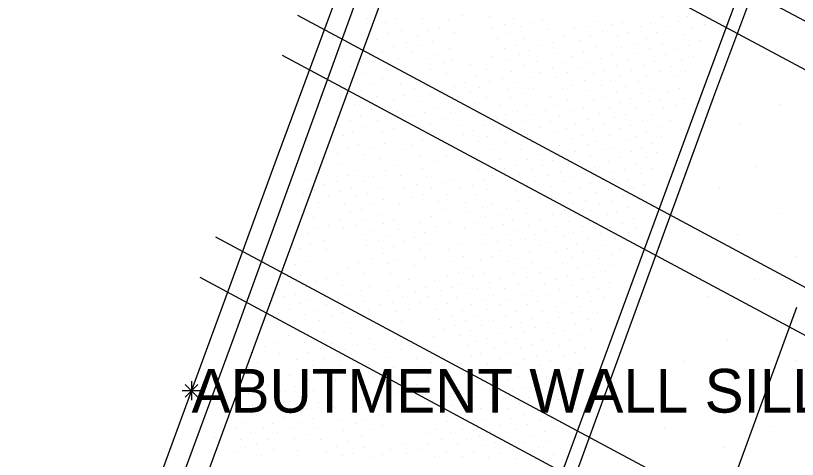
# Model space of a CAD drawing. Extents: x 1729983 to 1730242, y 468641 to 469019.
# Drawn here: x 1730044.55 to 1730076.74, y 468830.28 to 468848.55 of the extents above; entities that cross this region are included whole.
import ezdxf

# ---------------------------------------------------------------- set-up
doc = ezdxf.new("R2010")
doc.units = 0
for name, color, linetype in [('Default', 7, 'Continuous'), ('S_Bridge_Abutment_Bottom', 7, 'Continuous'), ('S_Curb_Type_1', 7, 'Continuous'), ('S_Ground_SpotElevation', 7, 'Continuous'), ('S_Misc_MiscFeature', 7, 'Continuous'), ('S_Misc_MiscItems', 7, 'Continuous'), ('S_Roadway_Edge_Pavement', 7, 'Continuous'), ('S_Text', 7, 'Continuous'), ('S_Utilities_AG_Communications', 7, 'Continuous')]:
    doc.layers.add(name, color=color, linetype=linetype)

# ---------------------------------------------------------------- blocks, each defined once
blk = doc.blocks.new('POINT_DISPLAY')
at = {"layer": 'Default'}
blk.add_line((0, 0), (0, 0), dxfattribs=at)

msp = doc.modelspace()

# ---------------------------------------------------------------- linework, layer by layer
at = {"layer": 'S_Bridge_Abutment_Bottom'}
msp.add_lwpolyline([(1730028.397, 468777.334), (1730030.386, 468778.233), (1730033.055, 468779.454), (1730033.218, 468779.896), (1730038.37, 468793.886), (1730045.609, 468813.805), (1730053.552, 468835.326), (1730061.264, 468856.585), (1730068.104, 468874.933), (1730077.288, 468899.639), (1730081.24, 468910.357), (1730081.674, 468911.604), (1730082.174, 468913.008), (1730079.112, 468916.385)], dxfattribs=at)
at = {"layer": 'S_Curb_Type_1'}
msp.add_lwpolyline([(1730127.344, 469003.745), (1730128.313, 469003.209), (1730129.005, 469001.957), (1730128.001, 468995.343), (1730121.966, 468978.7), (1730114.875, 468959.641), (1730107.952, 468940.794), (1730100.667, 468921.305), (1730089.464, 468890.124), (1730080.18, 468865.229), (1730072.814, 468845.368), (1730066.167, 468827.336), (1730059.271, 468808.011), (1730050.413, 468784.194), (1730032.961, 468736.85), (1730026.597, 468719.521), (1730017.926, 468696.116)], dxfattribs=at)
at = {"layer": 'S_Misc_MiscFeature'}
for p, q in [((1730084.047, 468844.582), (1730059.664, 468857.636)), ((1730083.323, 468842.964), (1730058.908, 468856.045)), ((1730081.008, 468835.237), (1730056.175, 468848.547)), ((1730080.253, 468833.664), (1730055.544, 468846.9)), ((1730077.695, 468826.086), (1730052.791, 468839.429)), ((1730076.906, 468824.473), (1730052.142, 468837.765)), ((1730073.388, 468827.447), (1730076.726, 468836.539))]:
    msp.add_line(p, q, dxfattribs=at)
msp.add_lwpolyline([(1730028.819, 468777.529), (1730031.975, 468779.199), (1730034.887, 468787.021), (1730045.144, 468814.963), (1730055.236, 468842.487), (1730058.712, 468851.879), (1730068.635, 468878.922), (1730072.147, 468888.181), (1730075.727, 468897.903), (1730078.619, 468905.503), (1730081.717, 468913.484), (1730079.668, 468915.827)], dxfattribs=at)
at = {"layer": 'S_Misc_MiscItems'}
for p, q in [((1730052.056, 468832.839), (1730051.532, 468833.363)), ((1730052.056, 468833.363), (1730051.532, 468832.839)), ((1730051.794, 468833.494), (1730051.794, 468832.708)), ((1730052.187, 468833.101), (1730051.401, 468833.101))]:
    msp.add_line(p, q, dxfattribs=at)
at = {"layer": 'S_Roadway_Edge_Pavement'}
msp.add_lwpolyline([(1730128.624, 468995.344), (1730122.317, 468978.183), (1730114.717, 468957.613), (1730108.465, 468940.563), (1730101.987, 468923.258), (1730100.18, 468918.245), (1730089.85, 468889.621), (1730080.624, 468864.761), (1730073.33, 468845.31), (1730066.507, 468826.616), (1730059.612, 468807.458), (1730050.88, 468783.514), (1730042.113, 468759.912), (1730034.557, 468739.828), (1730031.891, 468732.687), (1730026.743, 468718.512), (1730018.434, 468695.905)], dxfattribs=at)
at = {"layer": 'S_Utilities_AG_Communications'}
msp.add_lwpolyline([(1730120.945, 469004.632), (1730097.184, 468954.408), (1730085.556, 468926.546), (1730082.304, 468910.964), (1730034.658, 468781.323), (1729998.254, 468703.261)], dxfattribs=at)

# ---------------------------------------------------------------- block references
at = {"layer": 'S_Ground_SpotElevation'}
for p in [(1730062.952, 468848.542), (1730064.062, 468848.518), (1730071.178, 468848.493), (1730072.214, 468848.507), (1730059.055, 468848.442), (1730059.76, 468848.264), (1730060.209, 468848.413), (1730061.314, 468848.415), (1730062.367, 468848.381), (1730064.686, 468848.19), (1730065.048, 468848.443), (1730065.736, 468848.278), (1730066.234, 468848.397), (1730068.526, 468848.326), (1730069.149, 468848.179), (1730069.543, 468848.255), (1730070.689, 468848.204), (1730071.84, 468848.291), (1730072.92, 468848.169), (1730059.237, 468848.015), (1730060.426, 468847.932), (1730061.519, 468847.952), (1730061.988, 468848.067), (1730062.628, 468847.846), (1730064.139, 468848.033), (1730065.334, 468848.088), (1730066.45, 468847.984), (1730067.572, 468848.015), (1730068.055, 468848.1), (1730068.714, 468847.91), (1730069.776, 468847.862), (1730070.296, 468848.094), (1730070.936, 468847.869), (1730071.353, 468848.11), (1730072.432, 468848.046), (1730058.797, 468847.751), (1730059.427, 468847.553), (1730059.901, 468847.801), (1730061.081, 468847.675), (1730064.386, 468847.615), (1730064.887, 468847.821), (1730065.456, 468847.591), (1730067.119, 468847.677), (1730067.809, 468847.523), (1730068.228, 468847.732), (1730069.331, 468847.705), (1730070.52, 468847.612), (1730072.052, 468847.773), (1730072.756, 468847.537), (1730060.119, 468847.257), (1730060.629, 468847.453), (1730061.276, 468847.319), (1730061.714, 468847.483), (1730062.401, 468847.214), (1730065.128, 468847.312), (1730066.215, 468847.336), (1730066.67, 468847.451), (1730068.419, 468847.272), (1730069.499, 468847.254), (1730070.03, 468847.407), (1730070.658, 468847.204), (1730071.174, 468847.358), (1730072.258, 468847.31), (1730058.601, 468847.181), (1730059.67, 468847.025), (1730060.862, 468847.027), (1730061.913, 468846.966), (1730064.667, 468847.179), (1730065.304, 468846.929), (1730065.686, 468847.11), (1730066.878, 468847), (1730067.474, 468846.882), (1730067.953, 468847.065), (1730069.122, 468846.943), (1730070.172, 468847.001), (1730071.316, 468846.946), (1730071.819, 468847.169), (1730075.469, 468846.915), (1730058.749, 468846.658), (1730059.236, 468846.809), (1730059.976, 468846.61), (1730060.325, 468846.788), (1730061.45, 468846.781), (1730062.165, 468846.617), (1730062.556, 468846.756), (1730064.187, 468846.866), (1730064.778, 468846.683), (1730065.984, 468846.671), (1730067.09, 468846.634), (1730068.196, 468846.607), (1730068.624, 468846.787), (1730069.783, 468846.692), (1730070.856, 468846.647), (1730071.96, 468846.693), (1730072.45, 468846.874), (1730058.36, 468846.456), (1730061.638, 468846.317), (1730063.274, 468846.516), (1730063.957, 468846.335), (1730064.965, 468846.264), (1730065.502, 468846.502), (1730066.671, 468846.375), (1730067.748, 468846.421), (1730068.819, 468846.306), (1730069.287, 468846.509), (1730069.915, 468846.297), (1730070.411, 468846.488), (1730071.059, 468846.241), (1730071.547, 468846.438), (1730072.151, 468846.252), (1730058.516, 468846.018), (1730058.97, 468846.153), (1730059.641, 468845.96), (1730060.766, 468845.939), (1730062.305, 468846.154), (1730063.477, 468846.098), (1730064.602, 468845.973), (1730065.745, 468846.008), (1730066.128, 468846.186), (1730066.823, 468846.016), (1730067.267, 468846.219), (1730068.342, 468846.164), (1730069.464, 468846.057), (1730070.55, 468846.081), (1730071.673, 468846.044), (1730058.065, 468845.752), (1730059.179, 468845.753), (1730060.392, 468845.697), (1730061.462, 468845.674), (1730062.606, 468845.623), (1730063.04, 468845.799), (1730064.061, 468845.818), (1730065.23, 468845.787), (1730067.468, 468845.653), (1730067.969, 468845.87), (1730068.665, 468845.675), (1730069.049, 468845.858), (1730069.681, 468845.638), (1730070.207, 468845.833), (1730058.261, 468845.332), (1730058.765, 468845.483), (1730060.958, 468845.543), (1730061.626, 468845.285), (1730062.08, 468845.475), (1730063.269, 468845.388), (1730063.659, 468845.58), (1730064.796, 468845.513), (1730065.402, 468845.358), (1730065.859, 468845.544), (1730067.055, 468845.532), (1730068.163, 468845.483), (1730069.292, 468845.393), (1730070.333, 468845.339), (1730070.823, 468845.523), (1730071.435, 468845.363), (1730071.89, 468845.567), (1730057.906, 468845.118), (1730059.026, 468845.096), (1730059.423, 468845.231), (1730060.105, 468845.101), (1730060.566, 468845.262), (1730061.158, 468845.003), (1730062.357, 468844.964), (1730062.769, 468845.221), (1730063.926, 468845.158), (1730064.944, 468845.158), (1730066.584, 468845.219), (1730067.256, 468845.086), (1730068.356, 468845.079), (1730068.832, 468845.164), (1730069.432, 468844.967), (1730069.874, 468845.135), (1730070.614, 468844.993), (1730071.071, 468845.104), (1730072.077, 468845.116), (1730058.505, 468844.875), (1730059.193, 468844.676), (1730061.916, 468844.723), (1730063.457, 468844.922), (1730064.489, 468844.863), (1730065.589, 468844.866), (1730066.356, 468844.641), (1730066.745, 468844.845), (1730067.401, 468844.655), (1730067.928, 468844.74), (1730069.012, 468844.743), (1730070.118, 468844.779), (1730071.248, 468844.727), (1730071.728, 468844.837), (1730076.053, 468844.901), (1730058.732, 468844.38), (1730060.257, 468844.588), (1730060.941, 468844.396), (1730061.388, 468844.551), (1730062.111, 468844.309), (1730062.457, 468844.545), (1730063.614, 468844.522), (1730064.713, 468844.477), (1730065.215, 468844.599), (1730065.856, 468844.464), (1730066.938, 468844.411), (1730068.614, 468844.501), (1730069.214, 468844.358), (1730069.675, 468844.474), (1730070.766, 468844.461), (1730057.866, 468844.037), (1730058.323, 468844.239), (1730058.961, 468843.999), (1730059.431, 468844.227), (1730060.532, 468844.204), (1730061.639, 468844.073), (1730062.788, 468844.035), (1730063.82, 468844.005), (1730064.346, 468844.294), (1730065.413, 468844.2), (1730066.587, 468844.17), (1730067.599, 468844.118), (1730068.137, 468844.281), (1730068.791, 468844.114), (1730069.875, 468844.035), (1730070.37, 468844.218), (1730071.03, 468844), (1730071.5, 468844.237), (1730074.404, 468844.097), (1730058.43, 468843.779), (1730059.642, 468843.753), (1730060.095, 468843.891), (1730061.132, 468843.935), (1730063.357, 468843.8), (1730064.475, 468843.842), (1730064.92, 468843.93), (1730065.609, 468843.674), (1730066.134, 468843.94), (1730066.72, 468843.78), (1730067.222, 468843.894), (1730068.311, 468843.87), (1730069.423, 468843.886), (1730070.543, 468843.786), (1730057.596, 468843.335), (1730058.066, 468843.61), (1730061.293, 468843.441), (1730061.796, 468843.654), (1730062.47, 468843.396), (1730062.979, 468843.642), (1730063.59, 468843.372), (1730063.996, 468843.568), (1730065.808, 468843.348), (1730067.443, 468843.504), (1730067.883, 468843.607), (1730068.49, 468843.385), (1730068.99, 468843.593), (1730069.687, 468843.397), (1730070.106, 468843.552), (1730071.13, 468843.557), (1730058.242, 468843.07), (1730058.647, 468843.248), (1730059.283, 468843.117), (1730059.734, 468843.271), (1730060.475, 468843.04), (1730060.858, 468843.208), (1730064.248, 468843.051), (1730064.728, 468843.324), (1730065.345, 468843.027), (1730066.481, 468843.126), (1730066.93, 468843.19), (1730068.139, 468843.224), (1730068.718, 468843.042), (1730069.181, 468843.119), (1730070.325, 468843.121), (1730070.742, 468843.295), (1730057.815, 468842.88), (1730058.899, 468842.84), (1730061.166, 468842.757), (1730062.277, 468842.793), (1730063.341, 468842.74), (1730066.093, 468842.826), (1730067.192, 468842.771), (1730067.623, 468842.95), (1730068.218, 468842.806), (1730069.913, 468842.953), (1730070.537, 468842.701), (1730070.926, 468842.909), (1730056.87, 468842.521), (1730057.356, 468842.664), (1730057.97, 468842.463), (1730059.53, 468842.658), (1730060.144, 468842.372), (1730061.793, 468842.546), (1730064.014, 468842.412), (1730064.486, 468842.64), (1730065.135, 468842.379), (1730065.628, 468842.637), (1730066.651, 468842.594), (1730067.363, 468842.416), (1730067.783, 468842.544), (1730068.973, 468842.528), (1730069.402, 468842.688), (1730070.121, 468842.467), (1730057.067, 468842.08), (1730058.646, 468842.159), (1730059.794, 468842.157), (1730061.296, 468842.264), (1730063.604, 468842.204), (1730064.693, 468842.266), (1730065.828, 468842.223), (1730066.227, 468842.364), (1730066.968, 468842.099), (1730068.031, 468842.053), (1730068.404, 468842.312), (1730069.19, 468842.108), (1730069.64, 468842.225), (1730070.274, 468842.063), (1730070.766, 468842.234), (1730075.039, 468842.352), (1730056.65, 468841.808), (1730058.214, 468841.975), (1730058.854, 468841.733), (1730059.274, 468841.91), (1730060.386, 468841.952), (1730061.484, 468841.904), (1730062.594, 468841.804), (1730063.838, 468841.818), (1730064.18, 468841.97), (1730064.855, 468841.782), (1730065.304, 468842.015), (1730066.469, 468841.969), (1730067.517, 468841.903), (1730068.703, 468841.8), (1730069.803, 468841.747), (1730057.236, 468841.601), (1730057.774, 468841.714), (1730058.378, 468841.477), (1730059.493, 468841.454), (1730060.571, 468841.46), (1730061.052, 468841.592), (1730061.69, 468841.434), (1730062.251, 468841.678), (1730062.814, 468841.446), (1730063.374, 468841.562), (1730065.598, 468841.455), (1730065.966, 468841.717), (1730066.63, 468841.526), (1730067.101, 468841.71), (1730067.769, 468841.442), (1730068.238, 468841.638), (1730069.355, 468841.635), (1730069.993, 468841.433), (1730070.407, 468841.608), (1730073.519, 468841.464), (1730056.413, 468841.207), (1730056.86, 468841.344), (1730057.42, 468841.102), (1730057.908, 468841.32), (1730058.533, 468841.091), (1730059.04, 468841.243), (1730061.333, 468841.194), (1730062.329, 468841.193), (1730063.501, 468841.187), (1730063.965, 468841.382), (1730065.158, 468841.343), (1730067.339, 468841.256), (1730068.482, 468841.258), (1730068.961, 468841.377), (1730069.594, 468841.091), (1730057.007, 468840.856), (1730058.096, 468840.831), (1730059.281, 468840.826), (1730059.678, 468840.987), (1730060.371, 468840.764), (1730060.84, 468841.061), (1730061.948, 468840.896), (1730063.07, 468840.856), (1730064.181, 468840.83), (1730065.267, 468840.922), (1730065.724, 468841.078), (1730066.794, 468841.027), (1730067.473, 468840.818), (1730068.017, 468840.942), (1730068.591, 468840.786), (1730069.096, 468840.907), (1730070.229, 468840.971), (1730056.163, 468840.506), (1730058.33, 468840.461), (1730058.808, 468840.551), (1730062.124, 468840.545), (1730063.227, 468840.477), (1730063.783, 468840.638), (1730064.78, 468840.626), (1730067.145, 468840.54), (1730068.278, 468840.522), (1730069.313, 468840.45), (1730069.782, 468840.651), (1730056.834, 468840.231), (1730057.873, 468840.133), (1730058.959, 468840.162), (1730059.473, 468840.349), (1730060.117, 468840.143), (1730061.69, 468840.29), (1730063.894, 468840.291), (1730064.418, 468840.366), (1730065.015, 468840.129), (1730065.581, 468840.411), (1730066.18, 468840.129), (1730066.666, 468840.345), (1730067.704, 468840.329), (1730068.906, 468840.342), (1730069.975, 468840.182), (1730075.956, 468840.383), (1730055.884, 468839.852), (1730056.965, 468839.806), (1730057.437, 468839.92), (1730058.551, 468839.886), (1730059.708, 468839.979), (1730061.237, 468840.029), (1730061.893, 468839.877), (1730062.423, 468840.038), (1730063.022, 468839.837), (1730063.448, 468840.022), (1730064.125, 468839.816), (1730064.638, 468839.961), (1730065.668, 468839.903), (1730066.783, 468839.857), (1730067.306, 468840.077), (1730067.911, 468839.881), (1730068.451, 468840.083), (1730069.061, 468839.814), (1730069.534, 468839.98), (1730070.117, 468839.792), (1730056.581, 468839.557), (1730058.056, 468839.767), (1730058.845, 468839.521), (1730059.169, 468839.712), (1730060.331, 468839.724), (1730061.4, 468839.619), (1730063.771, 468839.551), (1730064.887, 468839.522), (1730065.205, 468839.709), (1730065.974, 468839.549), (1730066.381, 468839.711), (1730067.542, 468839.627), (1730068.642, 468839.569), (1730069.779, 468839.624), (1730074.258, 468839.532), (1730056.703, 468839.164), (1730057.245, 468839.295), (1730059.48, 468839.281), (1730059.957, 468839.449), (1730060.527, 468839.262), (1730060.985, 468839.429), (1730061.599, 468839.179), (1730062.806, 468839.175), (1730064.404, 468839.267), (1730065.536, 468839.323), (1730066.552, 468839.22), (1730067.111, 468839.44), (1730067.657, 468839.157), (1730068.15, 468839.367), (1730069.251, 468839.382), (1730056.262, 468838.962), (1730057.352, 468838.927), (1730058.99, 468839.077), (1730060.097, 468839.039), (1730061.162, 468838.933), (1730062.365, 468838.908), (1730063.913, 468839.107), (1730064.526, 468838.887), (1730064.979, 468839.065), (1730066.147, 468839.069), (1730066.826, 468838.831), (1730067.26, 468838.943), (1730068.374, 468838.882), (1730068.852, 468839.1), (1730069.458, 468838.92), (1730059.187, 468838.554), (1730059.709, 468838.774), (1730060.265, 468838.524), (1730061.391, 468838.569), (1730062.995, 468838.634), (1730064.165, 468838.635), (1730065.231, 468838.543), (1730065.731, 468838.824), (1730067.487, 468838.607), (1730067.924, 468838.781), (1730068.602, 468838.532), (1730069.081, 468838.7), (1730076.684, 468838.626), (1730056.071, 468838.304), (1730056.543, 468838.42), (1730058.688, 468838.368), (1730059.853, 468838.36), (1730060.992, 468838.248), (1730062.584, 468838.444), (1730063.258, 468838.194), (1730063.678, 468838.449), (1730064.801, 468838.434), (1730065.842, 468838.397), (1730066.534, 468838.193), (1730067.06, 468838.331), (1730068.179, 468838.271), (1730069.167, 468838.27), (1730055.171, 468837.88), (1730055.575, 468838.049), (1730057.782, 468837.942), (1730058.274, 468838.131), (1730058.887, 468837.93), (1730059.993, 468837.921), (1730062.782, 468837.971), (1730063.877, 468837.931), (1730065.045, 468837.92), (1730065.441, 468838.171), (1730066.124, 468837.963), (1730067.687, 468838.15), (1730068.822, 468838.011), (1730055.813, 468837.586), (1730056.296, 468837.855), (1730056.88, 468837.593), (1730057.347, 468837.738), (1730060.735, 468837.663), (1730061.791, 468837.658), (1730062.331, 468837.851), (1730063.356, 468837.791), (1730064.075, 468837.55), (1730064.48, 468837.74), (1730065.631, 468837.756), (1730066.767, 468837.693), (1730067.271, 468837.852), (1730067.905, 468837.664), (1730068.355, 468837.77), (1730069.006, 468837.555), (1730074.983, 468837.697), (1730055.32, 468837.332), (1730056.483, 468837.374), (1730058.027, 468837.444), (1730058.761, 468837.23), (1730059.141, 468837.413), (1730059.874, 468837.23), (1730060.327, 468837.402), (1730061.422, 468837.364), (1730062.038, 468837.226), (1730062.547, 468837.369), (1730062.905, 468837.533), (1730063.586, 468837.296), (1730064.69, 468837.293), (1730065.258, 468837.459), (1730065.818, 468837.235), (1730066.346, 468837.49), (1730066.954, 468837.266), (1730067.45, 468837.425), (1730068.571, 468837.331), (1730054.896, 468837.12), (1730055.622, 468836.964), (1730056.059, 468837.081), (1730057.113, 468837.11), (1730058.167, 468837.067), (1730060.478, 468837.002), (1730061.004, 468837.189), (1730061.527, 468836.966), (1730062.704, 468836.949), (1730063.101, 468837.101), (1730064.247, 468837.018), (1730065.42, 468837.085), (1730066.531, 468837.064), (1730067.633, 468836.994), (1730068.115, 468837.188), (1730068.817, 468836.925), (1730073.097, 468837.002), (1730055.108, 468836.763), (1730056.24, 468836.689), (1730056.644, 468836.852), (1730057.369, 468836.641), (1730057.827, 468836.842), (1730058.891, 468836.793), (1730059.565, 468836.633), (1730060.05, 468836.746), (1730061.193, 468836.745), (1730062.32, 468836.679), (1730063.334, 468836.659), (1730063.786, 468836.853), (1730064.492, 468836.647), (1730064.89, 468836.85), (1730065.619, 468836.651), (1730066.049, 468836.772), (1730067.191, 468836.754), (1730067.809, 468836.576), (1730068.279, 468836.778), (1730055.366, 468836.296), (1730055.815, 468836.446), (1730056.449, 468836.252), (1730056.871, 468836.4), (1730058.016, 468836.322), (1730059.064, 468836.405), (1730060.248, 468836.353), (1730060.711, 468836.457), (1730061.832, 468836.459), (1730062.96, 468836.415), (1730063.97, 468836.441), (1730065.126, 468836.352), (1730066.262, 468836.38), (1730066.8, 468836.571), (1730067.42, 468836.332), (1730068.52, 468836.343), (1730054.813, 468835.985), (1730056.002, 468835.952), (1730057.052, 468835.986), (1730057.609, 468836.169), (1730058.172, 468835.931), (1730058.674, 468836.174), (1730060.423, 468835.942), (1730062.009, 468836.04), (1730062.524, 468836.218), (1730063.078, 468835.975), (1730063.583, 468836.16), (1730064.226, 468836), (1730064.702, 468836.215), (1730065.853, 468836.088), (1730066.942, 468836.124), (1730068.101, 468836.031), (1730075.802, 468835.97), (1730055.566, 468835.841), (1730062.187, 468835.609), (1730062.667, 468835.793), (1730063.727, 468835.793), (1730064.976, 468835.688), (1730065.34, 468835.892), (1730065.962, 468835.723), (1730066.484, 468835.893), (1730067.615, 468835.891), (1730068.259, 468835.638), (1730055.78, 468835.384), (1730056.19, 468835.545), (1730057.255, 468835.555), (1730058.398, 468835.468), (1730061.751, 468835.336), (1730062.846, 468835.371), (1730063.275, 468835.597), (1730064.421, 468835.47), (1730065.511, 468835.487), (1730066.718, 468835.457), (1730067.142, 468835.59), (1730067.855, 468835.436), (1730055.22, 468835.104), (1730056.463, 468835.086), (1730057.577, 468835.052), (1730058.634, 468834.993), (1730059.113, 468835.273), (1730060.172, 468835.212), (1730060.829, 468834.977), (1730063.478, 468835.13), (1730063.975, 468835.257), (1730064.723, 468835.096), (1730065.163, 468835.261), (1730065.777, 468834.999), (1730066.235, 468835.223), (1730066.964, 468834.984), (1730067.351, 468835.175), (1730073.869, 468835.165), (1730054.314, 468834.67), (1730054.78, 468834.919), (1730055.423, 468834.652), (1730056.627, 468834.67), (1730057.098, 468834.855), (1730058.094, 468834.792), (1730059.347, 468834.781), (1730060.416, 468834.809), (1730061.532, 468834.649), (1730061.93, 468834.909), (1730063.142, 468834.945), (1730064.263, 468834.849), (1730064.901, 468834.656), (1730065.335, 468834.854), (1730066.421, 468834.726), (1730067.609, 468834.688), (1730067.988, 468834.889), (1730056.106, 468834.391), (1730057.275, 468834.414), (1730057.775, 468834.639), (1730058.409, 468834.417), (1730059.947, 468834.482), (1730061.038, 468834.439), (1730063.335, 468834.498), (1730063.701, 468834.633), (1730064.483, 468834.424), (1730065.513, 468834.388), (1730066.015, 468834.533), (1730066.577, 468834.335), (1730067.142, 468834.566), (1730076.697, 468834.367), (1730054.136, 468834.042), (1730054.497, 468834.271), (1730056.754, 468834.143), (1730057.941, 468834.146), (1730059.086, 468834.172), (1730060.123, 468834.078), (1730061.247, 468834.09), (1730061.665, 468834.252), (1730062.894, 468834.229), (1730063.975, 468834.179), (1730065.09, 468834.205), (1730066.175, 468834.148), (1730067.352, 468834.023), (1730067.796, 468834.232), (1730072.045, 468834.307), (1730055.838, 468833.729), (1730056.329, 468833.956), (1730057.001, 468833.782), (1730057.521, 468833.967), (1730059.301, 468833.7), (1730062.358, 468833.988), (1730063.048, 468833.81), (1730063.543, 468833.923), (1730064.171, 468833.763), (1730064.658, 468833.991), (1730065.237, 468833.674), (1730065.77, 468833.922), (1730066.898, 468833.806), (1730067.961, 468833.907), (1730054.255, 468833.635), (1730056.608, 468833.568), (1730057.729, 468833.537), (1730059.976, 468833.389), (1730061.041, 468833.379), (1730061.508, 468833.632), (1730062.14, 468833.431), (1730062.602, 468833.625), (1730063.761, 468833.516), (1730064.842, 468833.542), (1730065.994, 468833.47), (1730066.427, 468833.658), (1730067.052, 468833.414), (1730067.446, 468833.613), (1730074.802, 468833.519), (1730054.597, 468833.181), (1730054.941, 468833.302), (1730055.675, 468833.067), (1730056.056, 468833.266), (1730056.82, 468833.095), (1730060.545, 468833.176), (1730061.688, 468833.159), (1730062.845, 468833.096), (1730063.238, 468833.245), (1730063.901, 468833.133), (1730064.42, 468833.303), (1730065.029, 468833.099), (1730065.541, 468833.242), (1730066.674, 468833.169), (1730067.697, 468833.203), (1730053.678, 468832.725), (1730054.118, 468833.004), (1730055.196, 468832.959), (1730056.341, 468832.83), (1730058.625, 468832.812), (1730060.145, 468832.988), (1730061.296, 468832.935), (1730062.402, 468832.871), (1730063.511, 468832.822), (1730064.643, 468832.792), (1730065.699, 468832.831), (1730066.178, 468833.013), (1730066.891, 468832.723), (1730067.263, 468832.991), (1730053.2, 468832.508), (1730054.312, 468832.529), (1730054.755, 468832.703), (1730055.852, 468832.658), (1730057.025, 468832.623), (1730057.689, 468832.398), (1730058.793, 468832.406), (1730059.214, 468832.481), (1730062.521, 468832.483), (1730063.069, 468832.592), (1730064.124, 468832.622), (1730065.298, 468832.572), (1730066.437, 468832.51), (1730067.461, 468832.563), (1730072.996, 468832.414), (1730053.887, 468832.26), (1730054.472, 468832.1), (1730055.009, 468832.231), (1730056.036, 468832.251), (1730056.512, 468832.359), (1730058.359, 468832.163), (1730059.494, 468832.098), (1730059.872, 468832.308), (1730062.075, 468832.306), (1730063.701, 468832.358), (1730064.314, 468832.153), (1730064.805, 468832.365), (1730065.471, 468832.128), (1730065.949, 468832.33), (1730067.091, 468832.3), (1730053.404, 468832.062), (1730054.016, 468831.777), (1730055.562, 468831.995), (1730056.314, 468831.776), (1730056.776, 468831.967), (1730057.861, 468831.877), (1730058.547, 468831.744), (1730058.953, 468831.905), (1730062.346, 468831.848), (1730062.774, 468831.975), (1730063.385, 468831.79), (1730063.904, 468831.881), (1730064.956, 468831.963), (1730066.107, 468831.919), (1730066.653, 468832.059), (1730067.221, 468831.91), (1730053.587, 468831.544), (1730054.743, 468831.536), (1730055.109, 468831.739), (1730055.883, 468831.595), (1730056.959, 468831.53), (1730058.032, 468831.455), (1730059.173, 468831.493), (1730059.664, 468831.685), (1730061.839, 468831.505), (1730062.969, 468831.515), (1730064.094, 468831.422), (1730064.51, 468831.675), (1730065.174, 468831.49), (1730065.628, 468831.713), (1730066.345, 468831.435), (1730066.86, 468831.62), (1730071.277, 468831.603), (1730075.619, 468831.64), (1730052.716, 468831.19), (1730053.795, 468831.111), (1730054.227, 468831.384), (1730054.954, 468831.112), (1730055.316, 468831.38), (1730056.017, 468831.147), (1730056.538, 468831.309), (1730058.792, 468831.257), (1730061.452, 468831.351), (1730062.475, 468831.383), (1730063.132, 468831.102), (1730063.634, 468831.23), (1730064.753, 468831.184), (1730065.867, 468831.211), (1730054.446, 468830.907), (1730057.109, 468831.097), (1730057.757, 468830.822), (1730058.223, 468830.997), (1730060.495, 468830.935), (1730061.552, 468830.901), (1730062.081, 468831.079), (1730062.73, 468830.91), (1730063.782, 468830.84), (1730064.313, 468830.989), (1730064.906, 468830.782), (1730065.488, 468830.974), (1730066.537, 468831.011), (1730053.569, 468830.551), (1730054.028, 468830.771), (1730055.16, 468830.695), (1730056.163, 468830.651), (1730057.337, 468830.588), (1730058.429, 468830.532), (1730058.887, 468830.761), (1730059.658, 468830.497), (1730060.005, 468830.702), (1730060.638, 468830.526), (1730061.125, 468830.694), (1730062.288, 468830.597), (1730063.391, 468830.604), (1730064.49, 468830.533), (1730065.611, 468830.532), (1730066.082, 468830.76), (1730066.685, 468830.48), (1730073.762, 468830.745), (1730054.672, 468830.418), (1730058.009, 468830.427), (1730059.169, 468830.368), (1730061.797, 468830.386), (1730062.936, 468830.385), (1730064.024, 468830.358), (1730065.142, 468830.306), (1730066.294, 468830.313)]:
    msp.add_blockref('POINT_DISPLAY', p, dxfattribs=at)

# ---------------------------------------------------------------- texts
at = {"layer": 'S_Text'}
msp.add_text('ABUTMENT WALL SILL', height=1.8, dxfattribs=at).set_placement((1730051.794, 468832.201))

doc.saveas('drawing.dxf')
